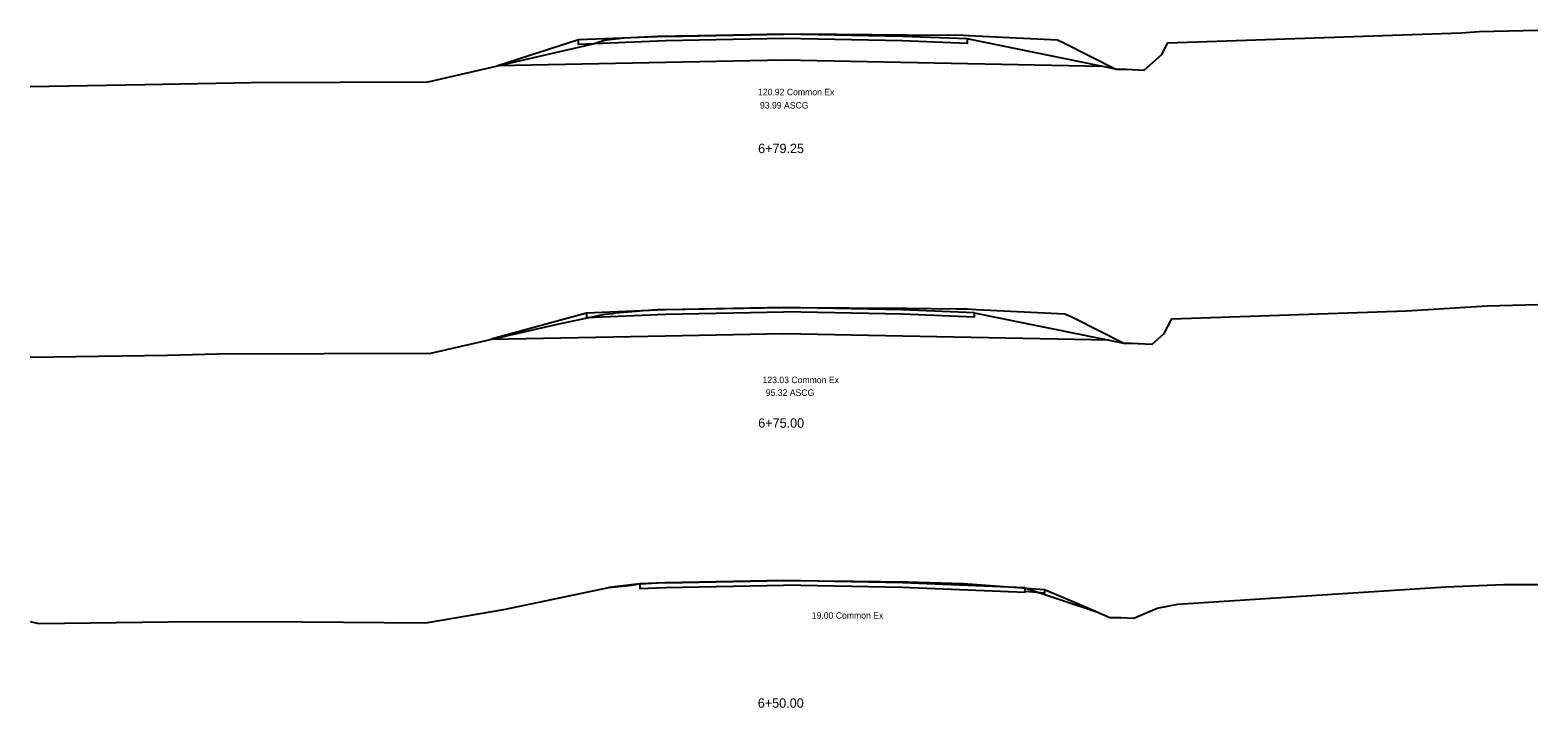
# Model space of a CAD drawing. Extents: x 2193811 to 2194294, y 863888 to 863998.
# Drawn here: x 2194154.3 to 2194294.3, y 863921.1 to 863984 of the extents above; entities that cross this region are included whole.
import ezdxf

# ---------------------------------------------------------------- set-up
doc = ezdxf.new("R2010")
doc.units = 0
for name, color, linetype in [('Approach', 7, 'Continuous'), ('H_V ANNOTATION', 7, 'Continuous'), ('S_Roadway_Centerline', 7, 'Continuous'), ('TEMPLATE', 7, 'Continuous')]:
    doc.layers.add(name, color=color, linetype=linetype)

msp = doc.modelspace()

# ---------------------------------------------------------------- linework, layer by layer
at = {"layer": 'S_Roadway_Centerline'}
for points in [[(2194154.3, 863978.77), (2194164.96, 863978.94), (2194174.82, 863979.14), (2194191.27, 863979.19), (2194206.58, 863982.72), (2194206.96, 863982.83), (2194207.63, 863983.06), (2194207.84, 863983.09), (2194209.45, 863983.26), (2194212.56, 863983.44), (2194214.3, 863983.46), (2194224.25, 863983.63), (2194225.95, 863983.64), (2194235.68, 863983.56), (2194240.95, 863983.51), (2194241.48, 863983.49), (2194249.69, 863983.09), (2194250.28, 863982.8), (2194255.11, 863980.36), (2194256.07, 863980.36), (2194257.74, 863980.28), (2194259.38, 863981.73), (2194259.95, 863982.81), (2194287.18, 863983.74), (2194288.84, 863983.85), (2194294.3, 863983.99)], [(2194154.3, 863953.62), (2194167.05, 863953.82), (2194171.7, 863953.92), (2194191.5, 863953.98), (2194203.27, 863956.7), (2194207.66, 863957.61), (2194208.42, 863957.69), (2194208.65, 863957.74), (2194210.18, 863957.85), (2194211.22, 863957.96), (2194212.55, 863958.04), (2194213.29, 863958.04), (2194224.24, 863958.24), (2194224.98, 863958.24), (2194235.7, 863958.16), (2194240.32, 863958.12), (2194241.38, 863958.1), (2194242.17, 863958.05), (2194250.38, 863957.64), (2194251.15, 863957.32), (2194255.87, 863954.93), (2194256.53, 863954.93), (2194258.49, 863954.84), (2194259.6, 863955.83), (2194260.31, 863957.17), (2194282.12, 863957.92), (2194289.61, 863958.4), (2194294.3, 863958.52)], [(2194154.3, 863929.08), (2194155.07, 863928.9), (2194167.13, 863929.04), (2194175.83, 863929.09), (2194190.95, 863928.95), (2194191.22, 863928.97), (2194198.28, 863930.19), (2194208.04, 863932.22), (2194209.94, 863932.41), (2194210.91, 863932.56), (2194211.46, 863932.59), (2194212.56, 863932.68), (2194219.14, 863932.79), (2194224.26, 863932.88), (2194230.78, 863932.83), (2194235.73, 863932.76), (2194240.97, 863932.61), (2194240.97, 863932.61), (2194240.98, 863932.61), (2194248.5, 863932.05), (2194251.79, 863930.65), (2194254.57, 863929.45), (2194255.58, 863929.45), (2194256.78, 863929.39), (2194258.94, 863930.32), (2194260.86, 863930.7), (2194285.76, 863932.3), (2194291.14, 863932.52), (2194294.3, 863932.52)], [(2194248.5, 863932.05), (2194248.5, 863931.71), (2194246.66, 863931.85)]]:
    msp.add_lwpolyline(points, dxfattribs=at)
at = {"layer": 'TEMPLATE'}
for p, q in [((2194213.3, 863983.41), (2194205.21, 863983.08)), ((2194213.3, 863983.41), (2194224.3, 863983.63)), ((2194224.3, 863983.63), (2194213.3, 863983.41)), ((2194235.3, 863983.41), (2194224.3, 863983.63)), ((2194241.3, 863983.17), (2194235.3, 863983.41)), ((2194205.21, 863983.08), (2194197.72, 863980.68)), ((2194207.3, 863983.17), (2194207.3, 863983.17)), ((2194224.3, 863983.21), (2194213.3, 863982.99)), ((2194235.3, 863982.99), (2194224.3, 863983.21)), ((2194255.11, 863980.36), (2194241.3, 863983.17)), ((2194224.3, 863981.21), (2194197.72, 863980.68)), ((2194253.83, 863980.62), (2194224.3, 863981.21)), ((2194205.97, 863957.72), (2194197.11, 863955.28)), ((2194213.3, 863957.6), (2194224.3, 863957.82)), ((2194235.3, 863957.6), (2194224.3, 863957.82)), ((2194241.97, 863957.75), (2194255.87, 863954.93)), ((2194210.91, 863932.56), (2194208.04, 863932.22)), ((2194213.3, 863932.66), (2194224.3, 863932.88)), ((2194213.3, 863932.24), (2194224.3, 863932.46)), ((2194235.3, 863932.24), (2194224.3, 863932.46)), ((2194246.66, 863932.2), (2194253.44, 863929.94))]:
    msp.add_line(p, q, dxfattribs=at)
for points in [[(2194213.3, 863982.99), (2194205.21, 863982.67), (2194205.21, 863983.08)], [(2194241.3, 863983.17), (2194241.3, 863982.75), (2194235.3, 863982.99)], [(2194241.97, 863957.75), (2194235.3, 863958.02), (2194224.3, 863958.24), (2194213.3, 863958.02), (2194205.97, 863957.72)], [(2194205.97, 863957.72), (2194205.97, 863957.31), (2194213.3, 863957.6)], [(2194241.97, 863957.75), (2194241.97, 863957.33), (2194235.3, 863957.6)], [(2194197.11, 863955.28), (2194213.3, 863955.6), (2194224.3, 863955.82), (2194235.3, 863955.6), (2194254.46, 863955.22)], [(2194246.66, 863932.2), (2194235.3, 863932.66), (2194224.3, 863932.88), (2194213.3, 863932.66), (2194210.91, 863932.56)], [(2194210.91, 863932.56), (2194210.91, 863932.14), (2194213.3, 863932.24)], [(2194246.66, 863932.2), (2194246.66, 863931.78), (2194235.3, 863932.24)]]:
    msp.add_lwpolyline(points, dxfattribs=at)

# ---------------------------------------------------------------- texts
at = {"layer": 'Approach'}
for s, p in [('120.92 Common Ex', (2194221.89, 863977.94)), ('93.99 ASCG', (2194222.07, 863976.71)), ('123.03 Common Ex', (2194222.31, 863951.21)), ('95.32 ASCG', (2194222.61, 863950.03)), ('19.00 Common Ex', (2194226.88, 863929.34))]:
    msp.add_text(s, height=0.6, dxfattribs=at).set_placement(p)
at = {"layer": 'H_V ANNOTATION'}
for s, p in [('6+79.25', (2194221.9, 863972.57)), ('6+75.00', (2194221.91, 863947.07)), ('6+50.00', (2194221.87, 863921.07))]:
    msp.add_text(s, height=0.875, dxfattribs=at).set_placement(p)

doc.saveas('drawing.dxf')
